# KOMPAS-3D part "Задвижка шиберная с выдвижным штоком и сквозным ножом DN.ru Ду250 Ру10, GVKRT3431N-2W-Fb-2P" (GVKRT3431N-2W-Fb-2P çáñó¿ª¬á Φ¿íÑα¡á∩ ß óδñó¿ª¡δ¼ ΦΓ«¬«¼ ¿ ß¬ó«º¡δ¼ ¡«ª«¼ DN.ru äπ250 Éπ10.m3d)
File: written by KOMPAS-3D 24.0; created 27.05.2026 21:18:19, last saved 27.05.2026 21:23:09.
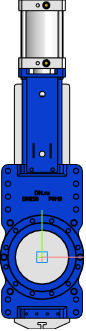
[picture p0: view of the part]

Document properties: Автор: DN.ru; Полное имя файла: C:\Работа\ГОТОВЫЕ ИСХОДНИКИ\GVKRT3431N-2W-Fb-2P Задвижка шиберная со сквозным ножом DN.ru Ду100-250 Ру16\DN250\GVKRT3431N-2W-Fb-2P Задвижка шиберная с выдвижным штоком и сквозным ножом DN.ru Ду250 Ру10.m3d

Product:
- Part/product: Задвижка шиберная с выдвижным штоком и сквозным ножом DN.ru Ду250 Ру10  | designation GVKRT3431N-2W-Fb-2P
    Масса: 86
    Раздел спецификации: Прочие изделия
    Примечание: D040-08533

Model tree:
1. Операция без истории:1

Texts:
  GVKRT3431N-2W-Fb-2P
